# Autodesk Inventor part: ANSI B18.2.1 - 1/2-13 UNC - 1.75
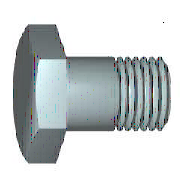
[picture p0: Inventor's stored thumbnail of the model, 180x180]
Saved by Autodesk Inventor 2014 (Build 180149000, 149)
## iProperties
Created: 2008-02
Part Number: ANSI B18.2.1 - 1/2-13 UNC - 1.75
Material: Steel, Mild
Description: Hex Cap Screw
Document SubType Name: Modeling
Standard: ANSI B18.2.1
Designer: floress
Standard Revision: 1996
Standards Organization: ANSI
Language: en-US
Size Designation: 1/2-13 UNC - 1.75
Categories: <MemberInstance><Categories><Category DisplayName="Fasteners" InternalName="e4da775c-781d-43d5-af7c-5136215cf5a6" Mnemonic="FSTN"><Category DisplayName="Bolts"
Density: 7.86 g/cm^3
Mass: 63.219 g
Surface Area: 28.6377 cm^2
Volume: 8.04314 cm^3
Appearance: Steel
IsCustomPart: 0
Author: floress
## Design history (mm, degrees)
sketch "Sketch1"
  geometry: L1 (0, 8.572)-(0, 6.35); L2 (4.877, 6.35)-(44.45, 6.35); L3 (44.45, 6.35)-(44.45, 0); L4 (44.45, 0)-(-0.635, 0); L5 (-9.652, 0)-(53.467, 0) reference; L6 (-0.635, 0)-(-0.635, 8.572); L7 (-0.635, 8.572)-(0, 8.572); L8 (4.877, 6.35)-(0.002, 6.35); L9 (0.002, 6.35)-(0, 6.35); L10 (0, -1.715)-(0, 10.287) reference
  constraints: 16 end point, 2 collinear, 2 perpendicular, 1 parallel
  dimensions: "d0" = 44.45 distance between parallel lines of L3 L1 (= NLG); "d1" = 39.5732 distance from line of L2.start L3 (= GEL); "d2" = 12.7 diameter of L2 L4 (= GD); "d9" = 0.6351 distance between parallel lines of L6 L1 (computed from SD); "d10" = 17.145 diameter of L7 L4 (= SD2); "d13" = 4.87436 distance of L2.start L8.end (computed from GAL); "d14" = 12.7 diameter of L9 L4 (= BDM)
revolve "Body" sketch "Sketch1" stored, may be unused: angle "d12" = 90 deg
sketch "Sketch2"
  geometry: L1 (0, 10.999)-(9.525, 5.499); L2 (9.525, 5.499)-(9.525, -5.499); L3 (9.525, -5.499)-(0, -10.999); L4 (0, -10.999)-(-9.525, -5.499); L5 (-9.525, -5.499)-(-9.525, 5.499); L6 (-9.525, 5.499)-(0, 10.999); 2 further points
  constraints: 12 end point, 1 coincident, 1 vertical, 11 other
  dimensions: "d11" = 19.05 distance between parallel lines of L5 L2 (= SW)
extrude "Head" join sketch "Sketch2" distance "d3" = 7.3025 (= KOH - SD); taper "d4" = 0 deg
sketch "Sketch4"
  geometry: L1 (-7.938, 9.525)-(-7.938, 10.999); L2 (-7.938, 10.999)-(-7.087, 10.999); L3 (-7.087, 10.999)-(-7.938, 9.525); L4 (-9.398, 0)-(0.825, 0) reference; L5 (-0.635, 10.999)-(-7.938, 10.999) reference; L6 (-7.938, 5.499)-(-7.938, 10.999) reference
  constraints: 6 end point, 2 collinear, 1 perpendicular, 1 vertical
  dimensions: "d5" = 30 deg angle of L3 L1 (= ANG1); "d19" = 19.05 diameter of L1.start L4 (= SW0)
revolve "Chamfer1" sketch "Sketch4" stored, may be unused: angle "d21" = 90 deg
workplane "Work Plane1"
fillet "Fillet2" dims "d63" = 0.635 (= R)
body "Solid1"
feature "Thread" dims "d15" = 39.5732 (= GEL), "d16" = 0
chamfer "Chamfer2" distance "d6" = 1.16332 (= -0.5 x SPD + 0.5 x GD); stored, may be unused: second distance "d7" = 1.16342 (computed from GUL), angle "d55" = 45 deg
other parameters: "NLG" = 44.45 [user parameter; used in 2 equation terms], "GD" = 12.7 (= NND) [user parameter; used in 2 equation terms], "BDM" = 12.7 [user parameter; used in 1 equation term], "KOH" = 7.9375 [user parameter; used in 1 equation term], "GEL" = 39.5732 [user parameter; used in 2 equation terms], "SW" = 19.05 [user parameter; used in 3 equation terms], "SW0" = 19.05 (= SW) [user parameter; used in 1 equation term], "SPD" = 10.37336 (= GD1) [user parameter; used in 1 equation term], "SD2" = 17.145 [user parameter; used in 1 equation term], "SD" = 0.635 [user parameter; used in 3 equation terms], "ANG1" = 30 deg [user parameter; used in 1 equation term], "GAL" = 4.87426 [user parameter; used in 1 equation term], "GUL" = 1.16332 [user parameter; used in 2 equation terms], "d8" = 0, "R" = 0.635 [user parameter; used in 1 equation term], "d58" = 0, "d62" = -43.92168 (= -NLG - SD + GUL), "THREADDIA" = 12.7 [user parameter], "TOA" = 30 deg [user parameter], "RR" = 0.762 [user parameter], "PTC" = 1.95385 (computed from TPU) [user parameter], "NND" = 12.7 [user parameter; used in 1 equation term], "E0" = 22.00275 (= 1.155 x SW) [user parameter], "SLG" = 0 [user parameter], "GD1" = 10.37336 [user parameter; used in 1 equation term]
